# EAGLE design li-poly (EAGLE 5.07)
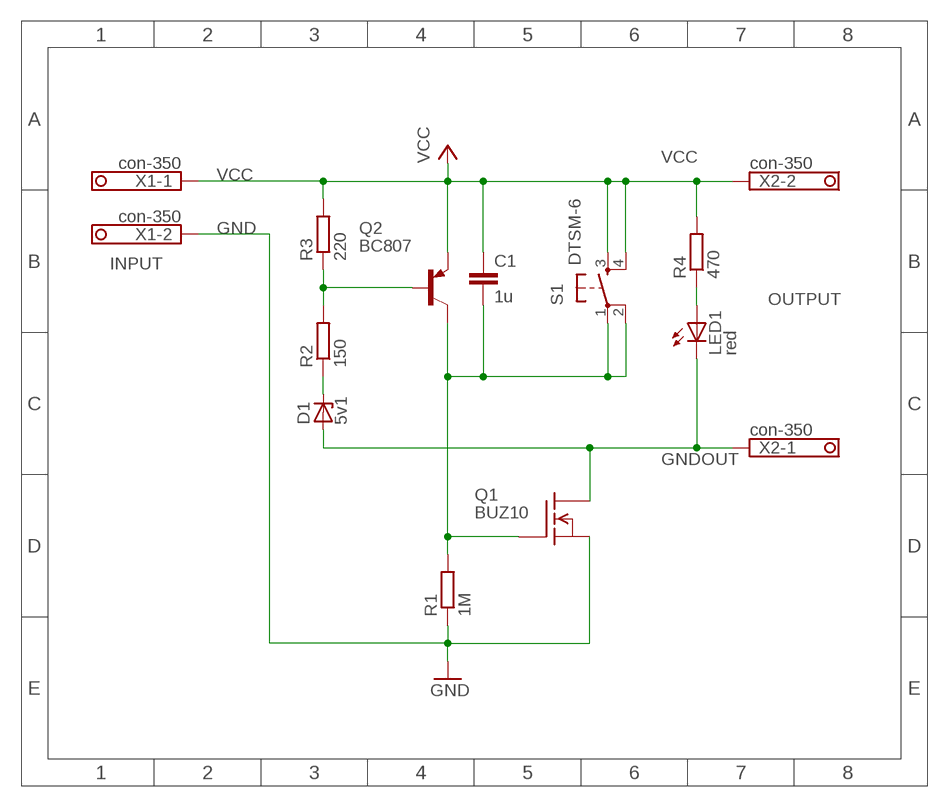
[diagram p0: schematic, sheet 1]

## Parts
C1  1u  C-EUC0805  [C0805]
D1  5v1  ZENER-DIODESOD80C  [SOD80C]
LED1  red  LEDCHIPLED_0805  [CHIPLED_0805]
Q1  BUZ10  BUZ10HN  [TO220_NONE]
Q2  BC807  BC807-16SMD  [SOT23-BEC]
R1  1M  R-EU_R1206  [R1206]
R2  150  R-EU_R0805  [R0805]
R3  220  R-EU_R0805  [R0805]
R4  470  R-EU_R0805  [R0805]
S1  DTSM-6  [DTSM-6]
X1  con-350  1751248  [1751248]
X2  con-350  1751248  [1751248]

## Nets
GND: Q1.3(S) R1.1 X1.2
GNDOUT: D1.A LED1.C Q1.2(D) X2.1
N$1: C1.2 Q1.1(G) Q2.C R1.2 S1.1 S1.2
N$2: Q2.B R2.2 R3.1
N$3: D1.C R2.1
N$4: LED1.A R4.1
VCC: C1.1 Q2.E R3.2 R4.2 S1.3 S1.4 X1.1 X2.2

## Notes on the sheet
- INPUT
- OUTPUT

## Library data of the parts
C1 = rcl:C-EU: CAPACITOR, European symbol
D1 = diode:ZENER-DIODE: Z-Diode
LED1 = led:LED: LED
Q1 = transistor-fet:BUZ10: N-Channel Enhancement MOSFET 50V; 20A; 0,080Ohm
Q2 = transistor-pnp:BC807*: PNP Transistror
R1-R4 = rcl:R-EU_: RESISTOR, European symbol
S1 = switch-tact:DTSM-6
X1 X2 = con-phoenix-350:1751248: MKDS 1/ 2-3,5 Printklemme

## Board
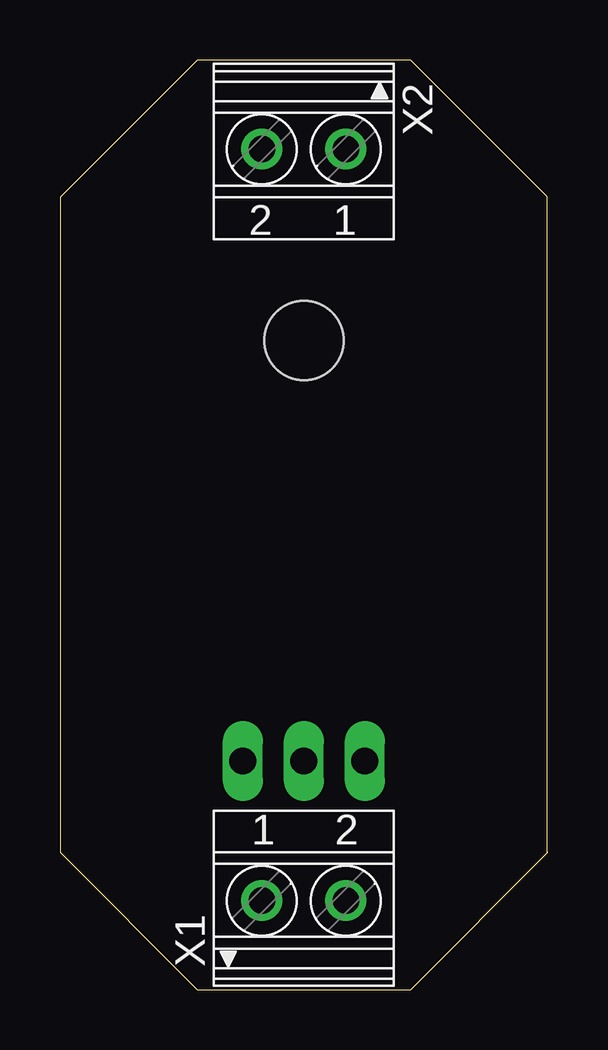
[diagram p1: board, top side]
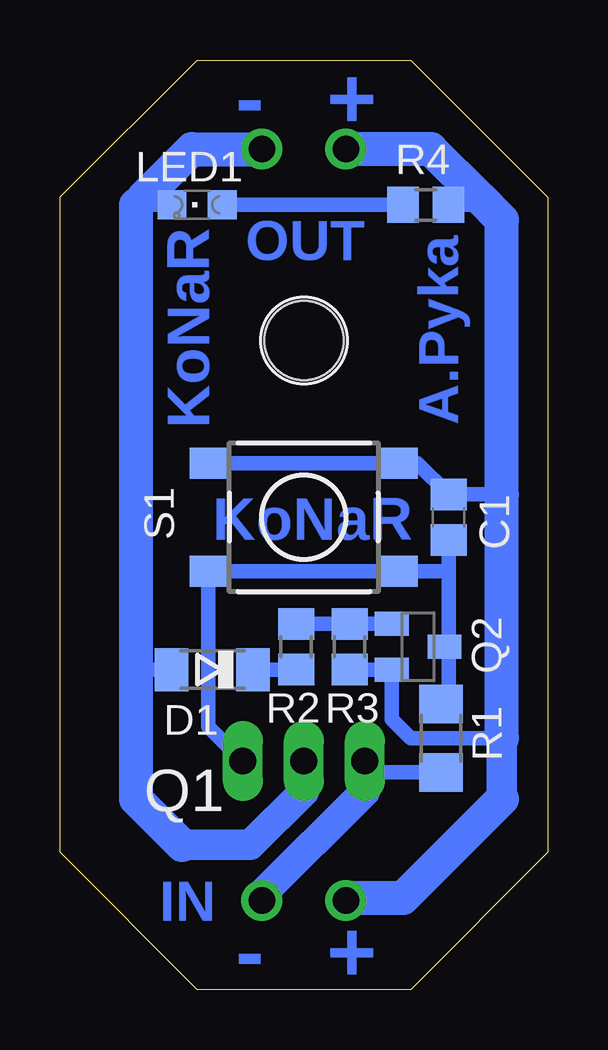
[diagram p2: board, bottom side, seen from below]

Size 20.32 x 38.73 mm. Coordinates in mm from the lower left corner, seen from the top.
Outline: 0,5.71 5.71,0 14.61,0 20.32,5.71 20.3,5.71 20.3,33.04 14.61,38.73 5.71,38.73 0,33.02 0,5.71
Copper layers (1*16): Top 0.035mm / dielectric 1.5mm / Bottom 0.035mm
Design rules "default": minimum track width 10mil, minimum drill 24mil, track to track 8mil, track to pad 8mil, pad to pad 8mil, via to via 8mil, smd to smd 8mil, copper to edge 40mil, drill to drill 8mil, minimum pad ring 10mil, minimum via ring 8mil, stop-mask expansion 4mil, vias tented up to drill 0mil, thermal gap 10mil

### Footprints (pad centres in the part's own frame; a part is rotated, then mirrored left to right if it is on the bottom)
C0805 = smd 1.3 x 1.5: 1 -0.95,0; 2 0.95,0
SOD80C = smd 1.4 x 1.8: A 1.7,0; C -1.7,0
CHIPLED_0805 = smd 1.2 x 1.2: A 0,-1.05; C 0,1.05
TO220_NONE = drill 1.118 long: 1 -2.54,-6.35; 2 0,-6.35; 3 2.54,-6.35 | hole 3.302: 0,11.176
SOT23-BEC = smd 1 x 1.4: B -0.95,-1.1; C 0,1.1; E 0.95,-1.1
R1206 = smd 1.6 x 1.803: 1 -1.422,0; 2 1.422,0
R0805 = smd 1.3 x 1.5: 1 -0.95,0; 2 0.95,0
DTSM-6 = smd 1.55 x 1.3: 1 -3.975,2.25; 2 3.975,2.25; 3 -3.975,-2.25; 4 3.975,-2.25
1751248 = drill 1.1 pad 1.7 round: 1 -1.75,-0.1; 2 1.75,-0.1

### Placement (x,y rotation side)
C1  4.13,19.68 270 bottom
D1  13.97,13.34 180 bottom
LED1  14.61,32.7 90 bottom
Q1  10.16,15.88 0 bottom
Q2  5.4,14.29 270 bottom
R1  4.45,10.48 90 bottom
R2  10.48,14.29 90 bottom
R3  8.26,14.29 270 bottom
R4  5.08,32.7 0 bottom
S1  10.16,19.68 180 bottom
X1  10.16,3.81 0 top
X2  10.16,34.92 180 top

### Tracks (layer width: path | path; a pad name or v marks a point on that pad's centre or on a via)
GND
  Bottom 0.61: R1.1 7.45,9.06 7.62,8.89
  Bottom 1.27: X1.2 11.91,3.96 7.62,8.26 7.62,8.89 Q1.3
GNDOUT
  Bottom 0.61: 17.15,13.34 D1.A | LED1.C 16.51,32.7 16.83,33.02
  Bottom 1.27: Q1.2 10.16,8.26 12.38,6.03 15.24,6.03 | 17.15,32.7 16.83,33.02
  Bottom 1.422: 15.24,6.03 17.15,7.94 17.15,13.34 17.15,32.7 | X2.1 14.82,35.02 16.83,33.02
N$1
  Bottom 0.61: 4.13,14.29 Q2.C | 4.13,14.29 4.13,17.43 | 4.13,17.43 S1.1 S1.2 14.13,10.96 Q1.1 | 4.13,17.43 C1.2 | 4.13,14.29 4.13,12.22 R1.2
N$2
  Bottom 0.61: R2.2 R3.1 Q2.B
N$3
  Bottom 0.61: D1.C R2.1
N$4
  Bottom 0.61: R4.1 LED1.A
VCC
  Bottom 0.61: R3.2 Q2.E 6.5,11.26 5.71,10.48 1.91,10.48 | S1.4 S1.3 5.43,21.93 C1.1 1.91,20.64 | R4.2 3.17,32.7 2.86,33.02
  Bottom 1.27: 1.91,7.94 1.91,10.48 | 8.31,3.81 X1.1
  Bottom 1.422: 1.91,10.48 1.91,20.64 1.91,32.07 2.86,33.02 4.86,35.02 X2.2 | 1.91,7.94 6.03,3.81 8.31,3.81

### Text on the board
Bottom: + | - | OUT | KoNaR | A.Pyka | KoNaR | IN | + | -
bDocu: + | - | OUT | KoNaR | A.Pyka | KoNaR | IN | + | -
